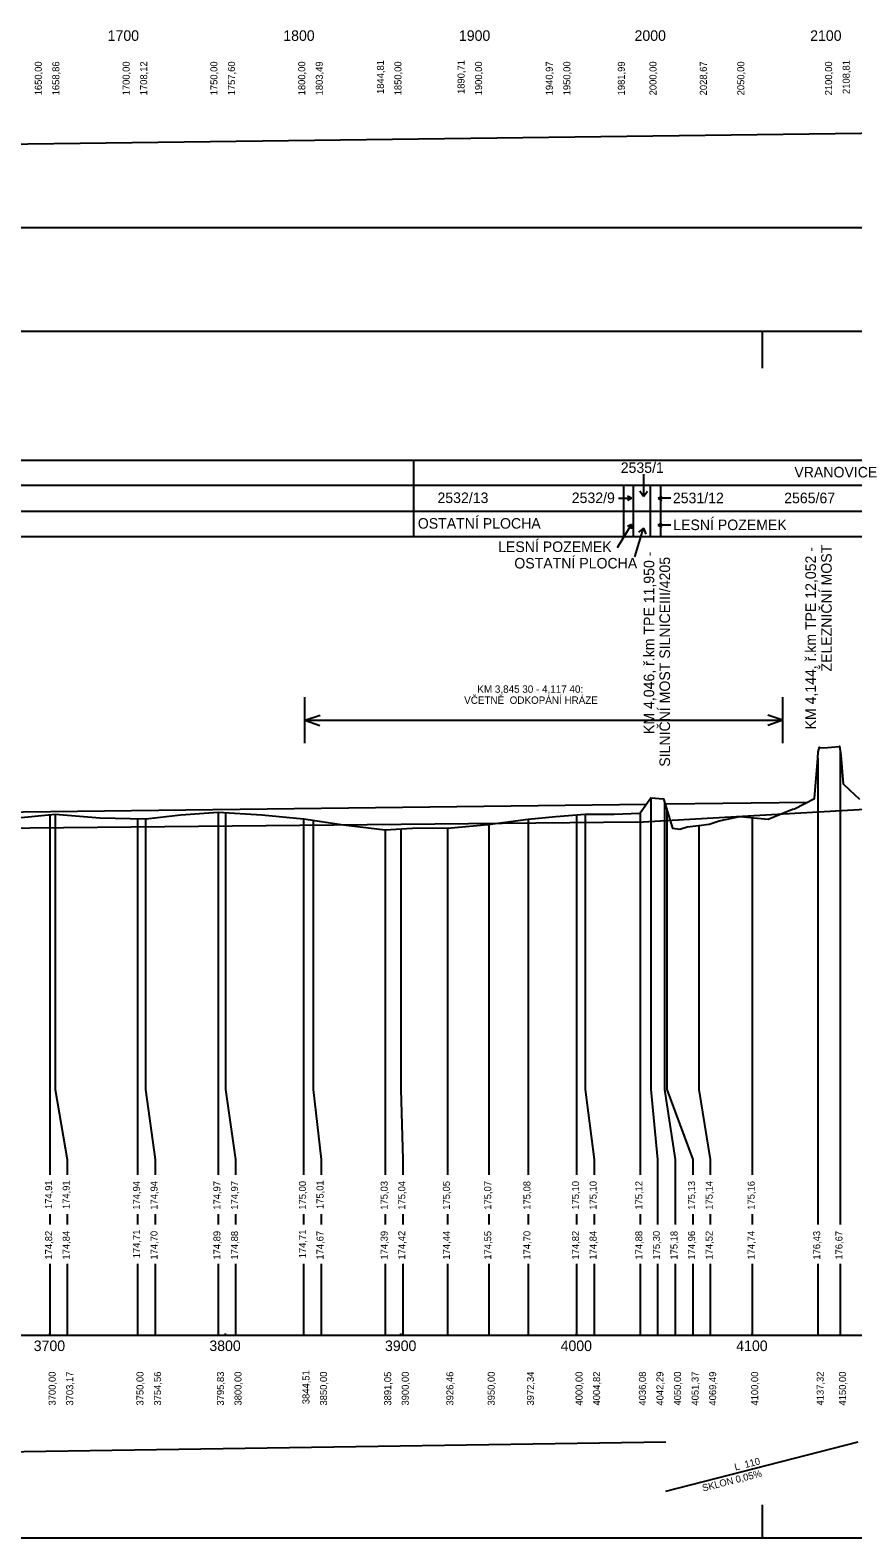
# Model space of a CAD drawing. Extents: x -614174 to -599765, y -1185887 to -1181080.
# Drawn here: x -602001 to -601533, y -1183929 to -1183070 of the extents above; entities that cross this region are included whole.
import ezdxf

# ---------------------------------------------------------------- set-up
doc = ezdxf.new("R2010")
doc.units = 0
for name, color, linetype in [('1', 7, 'Continuous'), ('11', 7, 'Continuous'), ('13', 7, 'Continuous'), ('56', 7, 'Continuous'), ('návrh', 7, 'Continuous')]:
    doc.layers.add(name, color=color, linetype=linetype)

msp = doc.modelspace()

# ---------------------------------------------------------------- linework, layer by layer
for p, q in [((-603189.79, -1183530.27), (-601650.08, -1183510.66)), ((-601639.5, -1183510.53), (-601638.41, -1183510.51)), ((-601638.41, -1183510.51), (-601558.55, -1183509.68))]:
    msp.add_line(p, q)
for points in [[(-603648.31, -1183155.82), (-601468.31, -1183127.82)], [(-602007.88, -1183518.59), (-601986.64, -1183516.36), (-601986.62, -1183516.36), (-601961.24, -1183518.57), (-601935.22, -1183519.09), (-601935.14, -1183519.09), (-601915.22, -1183516.75), (-601893.95, -1183515.29), (-601893.87, -1183515.29), (-601868.94, -1183516.82), (-601845.28, -1183519.02), (-601845.18, -1183519.03), (-601822.47, -1183522.52), (-601798.74, -1183525.38), (-601798.71, -1183525.38), (-601780.13, -1183524.25), (-601763.33, -1183524.41), (-601763.33, -1183524.41), (-601740.3, -1183522.29), (-601717.46, -1183519.28), (-601717.45, -1183519.28), (-601701.56, -1183517.8), (-601684.97, -1183516.37), (-601684.96, -1183516.37), (-601668.44, -1183516.37), (-601653.79, -1183515.8), (-601653.7, -1183515.58), (-601647.5, -1183507.16), (-601640.4, -1183507.67), (-601635.12, -1183524.4), (-601630.96, -1183525.03), (-601626.76, -1183523.62), (-601620.29, -1183522.81), (-601614.3, -1183522.08), (-601608.58, -1183520.27), (-601596.83, -1183517.79), (-601580.72, -1183519.25), (-601566.91, -1183513.58), (-601565.68, -1183513.45), (-601554.32, -1183507.45), (-601552.47, -1183484.54), (-601552.18, -1183480.94), (-601551.58, -1183478.21), (-601551.32, -1183478.42), (-601549, -1183478.71), (-601540.23, -1183477.84), (-601540.07, -1183477.71), (-601539.36, -1183482.86), (-601538.11, -1183499.18), (-601534.46, -1183502.59), (-601528.8, -1183507.97)], [(-601539.79, -1183479.76), (-601539.79, -1183673.18), (-601539.79, -1183713.18), (-601539.79, -1183721.76)], [(-601552.47, -1183484.53), (-601552.47, -1183673.18), (-601552.47, -1183713.18), (-601552.47, -1183721.76)], [(-601647.5, -1183507.16), (-601647.5, -1183673.18), (-601643.7, -1183713.18), (-601643.7, -1183721.76)], [(-601639.79, -1183509.63), (-601639.79, -1183673.18), (-601633.7, -1183713.18), (-601633.7, -1183721.76)], [(-601638.41, -1183513.98), (-601638.41, -1183673.18), (-601623.7, -1183713.18), (-601623.7, -1183721.76)], [(-601989.79, -1183516.69), (-601989.79, -1183673.18), (-601989.79, -1183713.18), (-601989.79, -1183721.76)], [(-601986.62, -1183516.36), (-601986.62, -1183673.18), (-601979.79, -1183713.18), (-601979.79, -1183721.76)], [(-601939.79, -1183519), (-601939.79, -1183673.18), (-601939.79, -1183713.18), (-601939.79, -1183721.76)], [(-601935.22, -1183519.09), (-601935.22, -1183673.18), (-601929.79, -1183713.18), (-601929.79, -1183721.76)], [(-601893.95, -1183515.29), (-601893.95, -1183673.18), (-601893.95, -1183713.18), (-601893.95, -1183721.76)], [(-601889.79, -1183515.54), (-601889.79, -1183673.18), (-601883.95, -1183713.18), (-601883.95, -1183721.76)], [(-601845.28, -1183519.02), (-601845.28, -1183673.18), (-601845.28, -1183713.18), (-601845.28, -1183721.76)], [(-601839.79, -1183519.86), (-601839.79, -1183673.18), (-601835.28, -1183713.18), (-601835.28, -1183721.76)], [(-601739.79, -1183522.22), (-601739.79, -1183673.18), (-601739.79, -1183713.18), (-601739.79, -1183721.76)], [(-601717.45, -1183519.28), (-601717.45, -1183673.18), (-601717.45, -1183713.18), (-601717.45, -1183721.76)], [(-601689.79, -1183516.78), (-601689.79, -1183673.18), (-601689.79, -1183713.18), (-601689.79, -1183721.76)], [(-601684.96, -1183516.37), (-601684.96, -1183673.18), (-601679.79, -1183713.18), (-601679.79, -1183721.76)], [(-601653.7, -1183515.58), (-601653.7, -1183673.18), (-601653.7, -1183713.18), (-601653.7, -1183721.76)], [(-601620.29, -1183522.81), (-601620.29, -1183673.18), (-601613.7, -1183713.18), (-601613.7, -1183721.76)], [(-601589.79, -1183518.43), (-601589.79, -1183673.18), (-601589.79, -1183713.18), (-601589.79, -1183721.76)], [(-601798.74, -1183525.38), (-601798.74, -1183673.18), (-601798.74, -1183713.18), (-601798.74, -1183721.76)], [(-601789.79, -1183524.84), (-601789.79, -1183673.18), (-601788.74, -1183713.18), (-601788.74, -1183721.76)], [(-601763.33, -1183524.41), (-601763.33, -1183673.18), (-601763.33, -1183713.18), (-601763.33, -1183721.76)], [(-601643.7, -1183721.76), (-601643.7, -1183750.11)], [(-601633.7, -1183721.76), (-601633.7, -1183750.11)], [(-601552.47, -1183721.76), (-601552.47, -1183750.11)], [(-601539.79, -1183721.76), (-601539.79, -1183750.11)], [(-601989.79, -1183744.25), (-601989.79, -1183750.11)], [(-601979.79, -1183744.25), (-601979.79, -1183750.11)], [(-601939.79, -1183744.25), (-601939.79, -1183750.11)], [(-601929.79, -1183744.25), (-601929.79, -1183750.11)], [(-601893.95, -1183744.25), (-601893.95, -1183750.11)], [(-601883.95, -1183744.25), (-601883.95, -1183750.11)], [(-601845.28, -1183744.25), (-601845.28, -1183750.11)], [(-601835.28, -1183744.25), (-601835.28, -1183750.11)], [(-601798.74, -1183744.25), (-601798.74, -1183750.11)], [(-601788.74, -1183744.25), (-601788.74, -1183750.11)], [(-601763.33, -1183744.25), (-601763.33, -1183750.11)], [(-601739.79, -1183744.25), (-601739.79, -1183750.11)], [(-601717.45, -1183744.25), (-601717.45, -1183750.11)], [(-601689.79, -1183744.25), (-601689.79, -1183750.11)], [(-601679.79, -1183744.25), (-601679.79, -1183750.11)], [(-601653.7, -1183744.25), (-601653.7, -1183750.11)], [(-601623.7, -1183744.25), (-601623.7, -1183750.11)], [(-601613.7, -1183744.25), (-601613.7, -1183750.11)], [(-601589.79, -1183744.25), (-601589.79, -1183750.11)], [(-601989.79, -1183772.6), (-601989.79, -1183813.18)], [(-601979.79, -1183772.6), (-601979.79, -1183813.18)], [(-601939.79, -1183772.6), (-601939.79, -1183813.18)], [(-601929.79, -1183772.6), (-601929.79, -1183813.18)], [(-601893.95, -1183772.6), (-601893.95, -1183813.18)], [(-601883.95, -1183772.6), (-601883.95, -1183813.18)], [(-601845.28, -1183772.6), (-601845.28, -1183813.18)], [(-601835.28, -1183772.6), (-601835.28, -1183813.18)], [(-601798.74, -1183772.6), (-601798.74, -1183813.18)], [(-601788.74, -1183772.6), (-601788.74, -1183813.18)], [(-601763.33, -1183772.6), (-601763.33, -1183813.18)], [(-601739.79, -1183772.6), (-601739.79, -1183813.18)], [(-601717.45, -1183772.6), (-601717.45, -1183813.18)], [(-601689.79, -1183772.6), (-601689.79, -1183813.18)], [(-601679.79, -1183772.6), (-601679.79, -1183813.18)], [(-601653.7, -1183772.6), (-601653.7, -1183813.18)], [(-601643.7, -1183772.6), (-601643.7, -1183813.18)], [(-601633.7, -1183772.6), (-601633.7, -1183813.18)], [(-601623.7, -1183772.6), (-601623.7, -1183813.18)], [(-601613.7, -1183772.6), (-601613.7, -1183813.18)], [(-601589.79, -1183772.6), (-601589.79, -1183813.18)], [(-601552.47, -1183772.6), (-601552.47, -1183813.18)], [(-601539.79, -1183772.6), (-601539.79, -1183813.18)], [(-603189.79, -1183897.17), (-601639.05, -1183873.97)], [(-601639.05, -1183901.97), (-601529.4, -1183873.97)]]:
    msp.add_lwpolyline(points)
at = {"layer": '1'}
for p, q in [((-601782.49, -1183358.51), (-601782.49, -1183314.75)), ((-601662.99, -1183358.51), (-601662.99, -1183329.34)), ((-601657.49, -1183358.51), (-601657.49, -1183329.34)), ((-601647.79, -1183358.51), (-601647.79, -1183329.34)), ((-601641.89, -1183358.51), (-601641.89, -1183329.34)), ((-601844.49, -1183462.93), (-601835.88, -1183460.09)), ((-601844.49, -1183462.93), (-601572.38, -1183462.93)), ((-601844.49, -1183462.93), (-601835.99, -1183465.92)), ((-601572.38, -1183462.93), (-601581, -1183460.09)), ((-601572.38, -1183462.93), (-601580.88, -1183465.92))]:
    msp.add_line(p, q, dxfattribs=at)
at = {"layer": '56'}
for p, q in [((-603189.79, -1183813.18), (-601189.79, -1183813.18)), ((-601989.79, -1183813.18), (-601989.79, -1183812.18)), ((-601889.79, -1183813.18), (-601889.79, -1183812.18)), ((-601789.79, -1183813.18), (-601789.79, -1183812.18)), ((-601689.79, -1183813.18), (-601689.79, -1183812.18)), ((-601589.79, -1183813.18), (-601589.79, -1183812.18))]:
    msp.add_line(p, q, dxfattribs=at)
at = {"layer": 'návrh'}
for p, q in [((-603790.54, -1183182.41), (-600749.89, -1183182.41)), ((-603264.06, -1183241.28), (-600744.06, -1183241.28)), ((-601584.06, -1183241.28), (-601584.06, -1183262.4)), ((-601651.67, -1183322.89), (-601651.67, -1183335.48)), ((-601651.67, -1183335.48), (-601653.85, -1183332.57)), ((-601651.67, -1183335.48), (-601649.48, -1183332.57)), ((-601665.92, -1183336.53), (-601658.64, -1183336.53)), ((-601658.64, -1183336.53), (-601660.82, -1183335.28)), ((-601658.64, -1183336.53), (-601660.82, -1183337.77)), ((-601643.44, -1183336.53), (-601641.26, -1183335.28)), ((-601636.16, -1183336.53), (-601643.44, -1183336.53)), ((-601643.44, -1183336.53), (-601641.26, -1183337.77)), ((-601666.48, -1183364.52), (-601658.64, -1183351.41)), ((-601658.64, -1183351.41), (-601660.83, -1183352.64)), ((-601658.64, -1183351.41), (-601658.69, -1183353.92)), ((-601643.44, -1183351.82), (-601641.26, -1183350.57)), ((-601656.63, -1183369.91), (-601651.67, -1183353.59)), ((-601651.67, -1183353.59), (-601654.6, -1183355.74)), ((-601651.67, -1183353.59), (-601650.42, -1183357.02)), ((-601636.16, -1183351.82), (-601643.44, -1183351.82)), ((-601643.44, -1183351.82), (-601641.26, -1183353.07)), ((-601844.49, -1183476.06), (-601844.49, -1183449.79)), ((-601572.38, -1183476.06), (-601572.38, -1183449.79)), ((-601655.34, -1183520.98), (-601518.77, -1183513.18)), ((-601655.34, -1183520.98), (-603189.79, -1183536.01)), ((-601584.06, -1183909.74), (-601584.06, -1183928.57)), ((-603264.06, -1183928.57), (-600744.06, -1183928.57))]:
    msp.add_line(p, q, dxfattribs=at)
for points in [[(-603189.79, -1183314.75), (-601203, -1183314.75), (-601203, -1183329.34), (-603189.79, -1183329.34)], [(-603189.79, -1183343.92), (-601203, -1183343.92), (-601203, -1183358.51), (-603189.79, -1183358.51)]]:
    msp.add_lwpolyline(points, dxfattribs=at)

# ---------------------------------------------------------------- texts
at = {"layer": '11'}
for s, rotation, p in [('1650,00', 90, (-601994.31, -1183107.06)), ('1658,86', 90, (-601984.31, -1183107.07)), ('1700,00', 90, (-601944.31, -1183107.06)), ('1708,12', 90, (-601934.31, -1183107.03)), ('1750,00', 90, (-601894.31, -1183107.06)), ('1757,60', 90, (-601884.31, -1183107.06)), ('1800,00', 90, (-601844.31, -1183107.06)), ('1803,49', 90, (-601834.31, -1183107.08)), ('1844,81', 90, (-601799.51, -1183106.3)), ('1850,00', 90, (-601789.51, -1183107.06)), ('1890,71', 90, (-601753.61, -1183106.3)), ('1900,00', 90, (-601743.61, -1183107.06)), ('1940,97', 90, (-601703.34, -1183107.07)), ('1950,00', 90, (-601693.34, -1183107.06)), ('1981,99', 90, (-601662.33, -1183107.08)), ('2000,00', 90, (-601644.31, -1183107.06)), ('2028,67', 90, (-601615.64, -1183107.07)), ('2050,00', 90, (-601594.31, -1183107.06)), ('2100,00', 90, (-601544.31, -1183107.06)), ('2108,81', 90, (-601534.31, -1183106.3)), ('174,91', 90, (-601988.42, -1183741.32)), ('174,91', 90, (-601978.42, -1183741.32)), ('174,94', 90, (-601938.42, -1183741.7)), ('174,94', 90, (-601928.42, -1183741.7)), ('174,97', 90, (-601892.59, -1183741.71)), ('174,97', 90, (-601882.59, -1183741.71)), ('175,00', 90, (-601843.91, -1183741.7)), ('175,01', 90, (-601833.91, -1183741.32)), ('175,03', 90, (-601797.37, -1183741.71)), ('175,04', 90, (-601787.37, -1183741.7)), ('175,05', 90, (-601761.96, -1183741.72)), ('175,07', 90, (-601738.42, -1183741.71)), ('175,08', 90, (-601716.08, -1183741.71)), ('175,10', 90, (-601688.42, -1183741.7)), ('175,10', 90, (-601678.42, -1183741.7)), ('175,12', 90, (-601652.34, -1183741.68)), ('175,13', 90, (-601622.34, -1183741.71)), ('175,14', 90, (-601612.34, -1183741.7)), ('175,16', 90, (-601588.42, -1183741.71)), ('174,82', 90, (-601988.42, -1183770.08)), ('174,84', 90, (-601978.42, -1183770.1)), ('174,71', 90, (-601938.42, -1183769.35)), ('174,70', 90, (-601928.42, -1183770.11)), ('174,89', 90, (-601892.59, -1183770.13)), ('174,88', 90, (-601882.59, -1183770.13)), ('174,71', 90, (-601843.91, -1183769.35)), ('174,67', 90, (-601833.91, -1183770.12)), ('174,39', 90, (-601797.37, -1183770.13)), ('174,42', 90, (-601787.37, -1183770.08)), ('174,44', 90, (-601761.96, -1183770.1)), ('174,55', 90, (-601738.42, -1183770.15)), ('174,70', 90, (-601716.08, -1183770.11)), ('174,82', 90, (-601688.42, -1183770.08)), ('174,84', 90, (-601678.42, -1183770.1)), ('174,88', 90, (-601652.34, -1183770.13)), ('175,30', 90, (-601642.34, -1183770.11)), ('175,18', 90, (-601632.34, -1183770.13)), ('174,96', 90, (-601622.34, -1183770.12)), ('174,52', 90, (-601612.34, -1183770.08)), ('174,74', 90, (-601588.42, -1183770.1)), ('176,43', 90, (-601551.1, -1183770.12)), ('176,67', 90, (-601538.42, -1183770.12)), ('3700,00', 90, (-601986.42, -1183853.21)), ('3703,17', 90, (-601976.42, -1183853.23)), ('3750,00', 90, (-601936.42, -1183853.21)), ('3754,56', 90, (-601926.42, -1183853.23)), ('3795,83', 90, (-601890.59, -1183853.23)), ('3800,00', 90, (-601880.59, -1183853.21)), ('3844,51', 90, (-601841.91, -1183852.45)), ('3850,00', 90, (-601831.91, -1183853.21)), ('3891,05', 90, (-601795.37, -1183853.26)), ('3900,00', 90, (-601785.37, -1183853.21)), ('3926,46', 90, (-601759.96, -1183853.23)), ('3950,00', 90, (-601736.42, -1183853.21)), ('3972,34', 90, (-601714.08, -1183853.21)), ('4000,00', 90, (-601686.42, -1183853.21)), ('4004,82', 90, (-601676.42, -1183853.19)), ('4036,08', 90, (-601650.34, -1183853.23)), ('4042,29', 90, (-601640.34, -1183853.23)), ('4050,00', 90, (-601630.34, -1183853.21)), ('4051,37', 90, (-601620.34, -1183853.23)), ('4069,49', 90, (-601610.34, -1183853.23)), ('4100,00', 90, (-601586.42, -1183853.21)), ('4137,32', 90, (-601549.1, -1183853.19)), ('4150,00', 90, (-601536.42, -1183853.21)), ('L  110', 14.32572, (-601599.39, -1183890.3)), ('SKLON 0,05%', 14.32572, (-601617.74, -1183902.21))]:
    msp.add_text(s, height=4, rotation=rotation, dxfattribs=at).set_placement(p)
at = {"layer": '13'}
for s, height, p in [('1700', 6, (-601956.8, -1183076.03)), ('1800', 6, (-601856.8, -1183076.03)), ('1900', 6, (-601756.8, -1183076.03)), ('2000', 6, (-601656.8, -1183076.03)), ('2100', 6, (-601556.8, -1183076.03)), ('2535/1', 6, (-601664.67, -1183322.08)), ('VRANOVICE', 6, (-601565.82, -1183324.66)), ('2532/13', 6, (-601769.02, -1183339.25)), ('2532/9', 6, (-601692.56, -1183339.25)), ('2531/12', 6, (-601634.99, -1183339.35)), ('2565/67', 6, (-601571.61, -1183339.35)), ('OSTATNÍ PLOCHA', 6, (-601780.22, -1183353.83)), ('LESNÍ POZEMEK', 6, (-601634.79, -1183354.65)), ('LESNÍ POZEMEK', 6, (-601734.48, -1183367.14)), ('OSTATNÍ PLOCHA', 6, (-601725.27, -1183376.52)), ('KM 3,845 30 - 4,117 40: ', 4.2, (-601746.32, -1183447.3)), ('VČETNĚ  ODKOPÁNÍ HRÁZE', 4.2, (-601753.82, -1183453.6)), ('3700', 6, (-601998.9, -1183822.18)), ('3800', 6, (-601898.9, -1183822.18)), ('3900', 6, (-601798.9, -1183822.18)), ('4000', 6, (-601698.9, -1183822.18)), ('4100', 6, (-601598.9, -1183822.18))]:
    msp.add_text(s, height=height, dxfattribs=at).set_placement(p)
for s, p in [('KM 4,046, ř.km TPE 11,950 - ', (-601645.6, -1183470.79)), ('KM 4,144, ř.km TPE 12,052 - ', (-601553.54, -1183468.2)), ('ŽELEZNIČNÍ MOST ', (-601544.54, -1183435.22)), ('SILNIČNÍ MOST SILNICEIII/4205  ', (-601636.6, -1183489.42))]:
    msp.add_text(s, height=6, rotation=90, dxfattribs=at).set_placement(p)

doc.saveas('drawing.dxf')
